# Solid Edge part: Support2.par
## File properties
Author: there
Template: Iso Metric Part.par
Last saved by: there
Revision: 16
Application: Solid Edge
Precisión: 0.990
Username: there
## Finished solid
Body 1: solid body, 19 faces, 48 edges, 30 vertices.
  Faces by surface: plane 15, cylinder 4
  Edges by curve: line 40, circle 8
Bounding box of the edges (mm): 56.697 x 3.840 x 54.781, from (-28.3486, -3.84, -38.7808) to (28.3486, 0, 16).
Cylindrical faces by radius (mm): R3 x2, R3.2 x1, R16 x1
Planar faces by outward normal: +x 2, +y 2, +z 2, -x 2, -y 1, -z 4, oblique 2
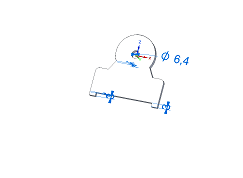
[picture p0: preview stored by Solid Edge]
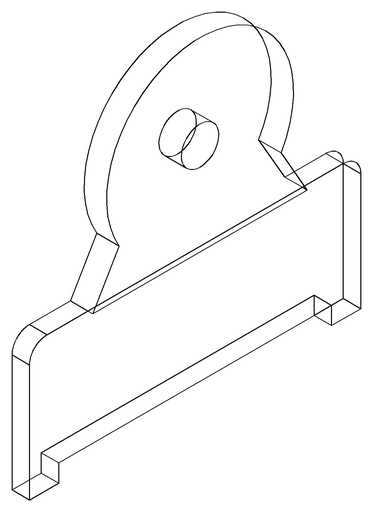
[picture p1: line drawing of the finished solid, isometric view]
